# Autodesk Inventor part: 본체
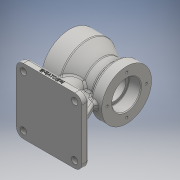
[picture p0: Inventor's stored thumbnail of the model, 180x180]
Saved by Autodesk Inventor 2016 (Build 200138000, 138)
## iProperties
Created: 2019-01
Part Number: 본체
Material: 일반
Document SubType Name: Modeling
Designer: 605-12
Density: 1 g/cm^3
Appearance: 기본값
Author: 605-12
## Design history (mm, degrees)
sketch "스케치1"
  geometry: L1 (0, 0)-(0, 40); L2 (0, 40)-(25, 40); L3 (25, 40)-(45.785, 28); L4 (45.785, 28)-(59.126, 28); L5 (59.126, 28)-(65, 35); L6 (65, 35)-(80, 35); L7 (80, 35)-(80, 0); L8 (80, 0)-(0, 0); L9 (0, 26)-(19, 26); L10 (20, 25)-(20, 16); L11 (20, 16)-(63, 16); L12 (63, 16)-(63, 19.4); L13 (63.6, 20)-(80, 20); A1 r 1 centre (19, 25) between (20, 25) and (19, 26); A2 r 0.6 centre (63.6, 19.4) between (63.6, 20) and (63, 19.4)
  constraints: 26 end point, 7 perpendicular, 4 point on circle, 4 tangent, 2 centre point, 2 parallel, 2 point on line, 1 horizontal, 1 vertical
  dimensions: "d0" = 80 diameter of L2 L8; "d1" = 56 diameter of L4 L8; "d2" = 70 diameter of L6 L8; "d4" = 30 deg angle of L4 L3; "d5" = 50 deg angle of L5 L4; "d6" = 25 distance of L1.end L2.end; "d7" = 80 distance between parallel lines of L7 L1; "d8" = 15 distance of L5.end L6.end; "d10" = 52 diameter of L9 L8; "d11" = 32 diameter of L11 L8; "d12" = 40 diameter of L13 L8; "d13" = 17 distance between parallel lines of L7 L12; "d14" = 20 distance between parallel lines of L10 L1; "d15" = 1 radius of A1; "d16" = 0.6 radius of A2
revolve "회전1" sketch "스케치1" stored, may be unused: angle "d17" = 90 deg
node "작업 평면1"
sketch "스케치2" dims "d32" = 10, "d39" = 10
  geometry: L1 (-15, -46)-(-87, -46); L2 (-97, -36)-(-97, 36); L3 (-87, 46)-(-15, 46); L4 (-5, 36)-(-5, -36); L5 (-5, -46)-(-97, 46); L6 (-97, -46)-(-5, 46); C1 r 16 at (-35, 0); C2 r 4.5 at (-87, -36); C3 r 4.5 at (-15, -36); C4 r 4.5 at (-15, 36); C5 r 4.5 at (-87, 36); A1 r 10 centre (-15, -36) between (-15, -46) and (-5, -36); A2 r 10 centre (-87, -36) between (-97, -36) and (-87, -46); A3 r 10 centre (-87, 36) between (-87, 46) and (-97, 36); A4 r 10 centre (-15, 36) between (-5, 36) and (-15, 46); 3 further points
  constraints: 12 end point, 9 centre point, 9 point on line, 8 point on circle, 8 tangent, 3 equal radius, 3 midpoint, 2 horizontal, 2 parallel, 1 horizontal alignment, 1 perpendicular, 1 vertical, 6 other
  dimensions: "d19" = 92 distance of L6.start L5.end; "d20" = 92 distance of L5.start L6.start; "d21" = 5 distance from line of L4 point (0, 0); "d22" = 32 diameter of C1; "d23" = 46 distance from line of L1 C1.centre; "d24" = 30 distance from line of C1.centre L4; "d25" = 10 radius of A1; "d26" = 9 diameter of C2; "d29" = 72 distance of C2.centre C3.centre; "d36" = 72 distance of C3.centre C4.centre
extrude "돌출1" join sketch "스케치2" distance "d41" = 10; taper "d42" = 0 deg
extrude "돌출2" join sketch "스케치2" stored distance "d43" = 10; taper "d44" = 0 deg
sketch "스케치3"
  geometry: L1 (87, -70)-(64.514, -21.778); L2 (64.514, -21.778)-(34.514, -21.778); L3 (34.514, -21.778)-(34.514, -70); L4 (34.514, -70)-(87, -70); L5 (87, -70)-(15, -70) reference; L6 (97, -80)-(97, -70) reference; 1 further point
  constraints: 8 end point, 1 collinear, 1 horizontal alignment, 1 perpendicular, 1 vertical
  dimensions: "d45" = 10 distance from line of L1.start L6; "d46" = 25 deg angle of L6 L1; "d47" = 48.22172 distance of L2.end L3.end; "d48" = 30 distance of L1.end L2.end
extrude "돌출3" join sketch "스케치3" stored distance "d49" = 10; taper "d50" = 0 deg
sketch "스케치4" dims "d51" = 66
  geometry: 6 further points
  constraints: 2 vertical alignment, 1 coincident, 7 other
  dimensions: "d54" = 360 deg dimension on point (0, 0) point (0, 33) (derived)
hole "구멍1" sketch "스케치4" at (0, 33), (-33, 0), (0, -33), (33, 0) diameter "d56" = 3.242; stored, may be unused: countersink angle "d60" = 90 deg, drill point angle "d62" = 118 deg; dims "d57" = 9, "d58" = 4, "d59" = 2, "d61" = 11
sketch "스케치5" dims "d63" = 55
  geometry: 6 further points
  constraints: 2 vertical alignment, 1 coincident, 7 other
  dimensions: "d66" = 360 deg dimension on point (0, 0) point (0, 27.5) (derived)
hole "구멍2" sketch "스케치5" at (0, 27.5), (-27.5, 0), (0, -27.5), (27.5, 0) diameter "d68" = 3.242; stored, may be unused: countersink angle "d72" = 90 deg, drill point angle "d74" = 118 deg; dims "d69" = 9, "d70" = 4, "d71" = 2, "d73" = 11
sketch "스케치6"
  geometry: L1 (0, 10)-(72, 10) reference; L2 (-10, 0)-(-10, 10) reference; L3 (72, 0)-(82, 0) reference; 2 further points
  constraints: 1 other
  dimensions: "d76" = 46 distance from line of point (36, 4) L2; "d77" = 4 distance from line of L3 point (36, 4)
feature "엠보싱1" sketch "스케치6" dims "d19" = 92, "d20" = 92, "d21" = 5, "d22" = 32, "d23" = 46, "d24" = 30, "d25" = 10, "d26" = 9, "d29" = 72, "d36" = 72, "d78" = 0.5, "d79" = 0
fillet "모깎기1" dims "d80" = 3
fillet "모깎기2" dims "d81" = 3
chamfer "모따기2" distance "d85" = 1; stored, may be unused: second distance "d86" = 2, angle "d87" = 45 deg
node "솔리드1"
